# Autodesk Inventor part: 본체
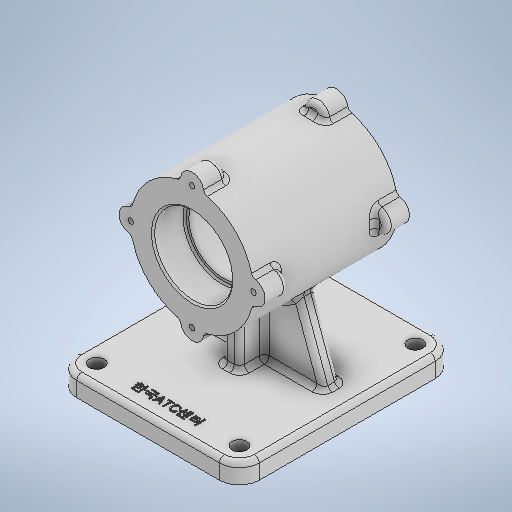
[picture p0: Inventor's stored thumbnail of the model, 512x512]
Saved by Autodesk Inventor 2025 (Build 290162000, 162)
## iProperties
Created: 2024-08
Part Number: 본체
Material: 일반
Document SubType Name: Modeling
Designer: onair
Density: 1 g/cm^3
Appearance: 기본값
Author: onair
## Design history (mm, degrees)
sketch "스케치1"
  geometry: L1 (43, 65)-(-43, 65); L2 (-55, 53)-(-55, -53); L3 (-43, -65)-(43, -65); L4 (55, -53)-(55, 53); L5 (55, 65)-(-55, -65); L6 (-55, 65)-(55, -65); A1 r 12 centre (43, 53) between (55, 53) and (43, 65); A2 r 12 centre (-43, 53) between (-43, 65) and (-55, 53); A3 r 12 centre (-43, -53) between (-55, -53) and (-43, -65); A4 r 12 centre (43, -53) between (43, -65) and (55, -53); 1 further point
  constraints: 12 end point, 8 point on circle, 8 point on line, 8 tangent, 4 centre point, 3 equal radius, 2 midpoint, 2 parallel, 1 horizontal, 1 perpendicular
  dimensions: "d0" = 130 distance of L6.start L5.end; "d1" = 110 distance of L5.end L6.end; "d2" = 12 radius of A1
extrude "돌출1" new body sketch "스케치1" distance "d3" = 12; taper "d4" = 0 deg
sketch "스케치2"
  geometry: A1 r 12 centre (-43, 53) between (-43, 65) and (-55, 53) reference; A2 r 12 centre (43, 53) between (55, 53) and (43, 65) reference; A3 r 12 centre (43, -53) between (43, -65) and (55, -53) reference; A4 r 12 centre (-43, -53) between (-55, -53) and (-43, -65) reference; 5 further points
  constraints: 4 coincident
hole "구멍1" sketch "스케치2" at (-43, 53), (43, 53), (43, -53), (-43, -53) diameter "d5" = 9; stored, may be unused: countersink angle "d9" = 90 deg, drill point angle "d11" = 120 deg; dims "d6" = 8, "d7" = 4, "d8" = 2, "d10" = 10
node "작업 평면1"
sketch "스케치4"
  geometry: L1 (43, -27.058)-(43, 162.351) reference; L2 (0, 0)-(86, 0) reference; C1 r 37 at (43, 82); 2 further points
  constraints: 1 centre point, 1 midpoint, 1 point on line
  dimensions: "d15" = 37 radius of C1; "d16" = 82 distance of point (43, 0) C1.centre
extrude "돌출2" join sketch "스케치4" stored distance "d17" = 87; taper "d18" = 0 deg
sketch "스케치5"
  geometry: L1 (137.943, -5)-(-51.616, -5); L2 (0, 65)-(12, 65) reference; L3 (45, -48.5)-(119, -48.5) reference; L4 (119, 38.5)-(45, 38.5) reference; L5 (82, 74.731)-(82, -76.192); L6 (0, -106.377)-(0, 104.915) reference; L7 (105.5, 38.5)-(82, 38.5); L8 (82, 38.5)-(82, 19.5); L9 (82, 19.5)-(104.5, 19.5); L10 (105.5, 20.5)-(105.5, 38.5); L11 (103, 19.5)-(82, 19.5); L12 (82, 19.5)-(82, -29.5); L13 (82, -29.5)-(103, -29.5); L14 (103, -29.5)-(103, 19.5); L15 (105.5, -30.5)-(105.5, -48.5); L16 (82, -29.5)-(104.5, -29.5); L17 (105.5, -48.5)-(82, -48.5); L18 (82, -48.5)-(82, -29.5); A1 r 1 centre (104.5, 20.5) between (104.5, 19.5) and (105.5, 20.5); A2 r 1 centre (104.5, -30.5) between (105.5, -30.5) and (104.5, -29.5); 7 further points
  constraints: 28 end point, 8 point on line, 4 parallel, 4 point on circle, 4 symmetric about line, 4 tangent, 3 horizontal, 2 centre point, 2 perpendicular, 1 equal radius, 1 vertical, 1 other
  dimensions: "d19" = 70 distance between parallel lines of L2 L1; "d20" = 82 distance between parallel lines of L6 L5; "d21" = 19 distance of point (105.5, 19.5) L7.start; "d22" = 47 diameter of L10 L5; "d23" = 42 diameter of L14 L5; "d24" = 1 radius of A1
revolve "회전1" sketch "스케치5" stored, may be unused: angle "d25" = 90 deg
chamfer "모따기1" distance "d26" = 1; stored, may be unused: second distance "d27" = 2, angle "d28" = 45 deg
sketch "스케치6"
  geometry: L1 (0, -105.8)-(0, 60.8) reference; C1 r 7 at (0, 37); 2 further points
  constraints: 1 centre point, 1 point on line, 1 vertical alignment, 1 other
  dimensions: "d29" = 7 radius of C1
extrude "돌출3" join sketch "스케치6" distance "d30" = 14; taper "d31" = 0 deg
fillet "모깎기1" dims "d35" = 3
fillet "모깎기2" dims "d36" = 3
sketch "스케치7" dims "d37" = 37
  geometry: L1 (43, -25.2)-(43, 151.2) reference; C1 r 24.5 at (43, 82) reference; 3 further points
  constraints: 1 coincident, 1 point on line, 1 vertical alignment, 2 other
hole "구멍2" sketch "스케치7" at (43, 119) diameter "d38" = 3.242; stored, may be unused: countersink angle "d42" = 82 deg, drill point angle "d44" = 120 deg; dims "d39" = 8, "d40" = 3.023, "d41" = 2, "d43" = 10
sketch "스케치8"
  geometry: L1 (81.5, 0)-(81.5, 12) reference; L2 (81.5, 0)-(81.5, 12) reference; L3 (-4.5, 12)-(4.5, 12) reference; L4 (81.5, 12)-(90.5, 12) reference; L5 (81.5, 12)-(90.5, 12) reference; L6 (-4.5, 12)-(4.5, 12) reference; L7 (86, 12)-(98, 12) reference; L8 (98, 12)-(86, 12) reference; L9 (86, 12)-(0, 12) reference; L10 (0, 12)-(-12, 12) reference; L11 (-12, 12)-(0, 12) reference; L12 (0, 12)-(86, 12) reference; L13 (84, 12)-(67.161, 58.264); L14 (98, 0)-(98, 12) reference; L15 (43, 92.388)-(43, -14.668); L16 (2, 12)-(18.839, 58.264); C1 r 21 at (43, 82) reference; 1 further point
  constraints: 6 end point, 2 point on line, 2 symmetric about line, 1 vertical
  dimensions: "d48" = 110 deg angle of L12 L13; "d49" = 14 distance from line of L14 L13.start
  node "투영된 루프3"
sketch "스케치9"
  geometry: L1 (-5, -15)-(5, -15); L2 (5, -15)-(5, 25); L3 (5, 25)-(-5, 25); L4 (-5, 25)-(-5, -15); L5 (0, 91)-(0, -91) reference; L6 (-43, -65)-(43, -65) reference; 1 further point
  constraints: 8 end point, 2 parallel, 1 horizontal, 1 perpendicular, 1 other
  dimensions: "d50" = 10 distance of L2.end L3.end; "d51" = 40 distance of L3.end L1.start; "d52" = 50 distance between parallel lines of L6 L1
extrude "돌출4" join sketch "스케치9" stored distance "d53" = 14; taper "d54" = 0 deg
fillet "모깎기3" dims "d55" = 3
feature "리브1" dims "d57" = 1, "d58" = 10, "d59" = 0, "d60" = 0, "d61" = 1, "d62" = 1
feature "리브2" dims "d63" = 1, "d64" = 10, "d65" = 0, "d66" = 0, "d67" = 1, "d68" = 1
fillet "모깎기5" dims "d69" = 3
fillet "모깎기6" dims "d70" = 3
fillet "모깎기7" dims "d71" = 3
sketch "스케치10"
  geometry: L1 (-43, -65)-(43, -65) reference; L2 (0, 91)-(0, -91) reference; 2 further points
  constraints: 1 point on line, 1 other
  dimensions: "d72" = 12 distance from line of L1 point (0, -53)
feature "엠보싱1" sketch "스케치10" dims "d0" = 130, "d1" = 110, "d2" = 12, "d73" = 0.5, "d74" = 0
node "솔리드1"
pattern_circular "원형 패턴1" dims angle "d33" = 360 deg
mirror "미러1"
pattern_circular "원형 패턴2" dims angle "d46" = 360 deg
mirror "미러2"
node "투영된 루프2"
feature "A9D066F2-1C7D-4E18-AEED-F7BC21143FA4" dims "d5" = 9, "d6" = 8, "d7" = 4, "d8" = 2, "d9" = 90 deg, "d10" = 10, "d11" = 120 deg
